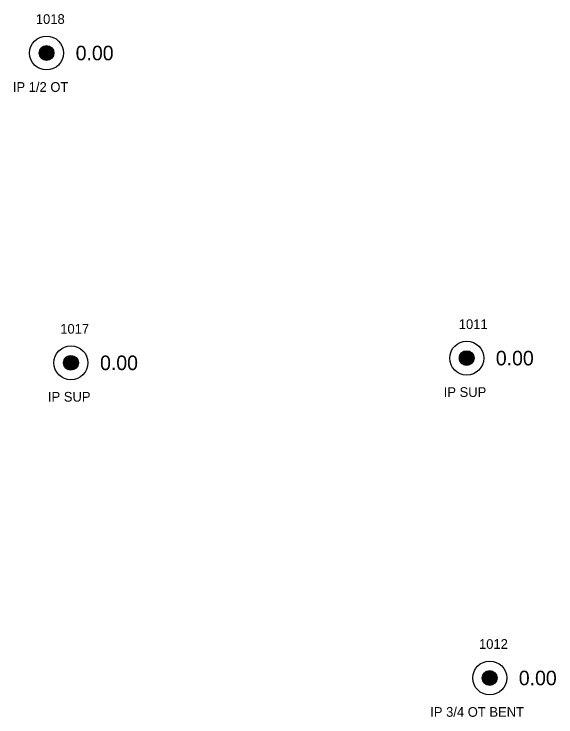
# Model space of a CAD drawing. Extents: x 1529475 to 1532053, y 876698 to 877911.
# Drawn here: x 1529474.6 to 1529530.4, y 877491.7 to 877564.1 of the extents above; entities that cross this region are included whole.
import ezdxf

# ---------------------------------------------------------------- set-up
doc = ezdxf.new("R2010")
doc.units = 0
for name, color, linetype in [('RD_EX_DV_Prop_txCode', 7, 'Continuous'), ('RD_EX_DV_PropPin', 7, 'Continuous'), ('RD_EX_TX_DV_Prop_ELEV', 7, 'Continuous'), ('RD_SMD_Locator', 7, 'Continuous')]:
    doc.layers.add(name, color=color, linetype=linetype)

msp = doc.modelspace()

# ---------------------------------------------------------------- linework, layer by layer
at = {"layer": 'RD_EX_DV_PropPin'}
for p, q in [((1529477.764, 877559.334), (1529477.764, 877560.815)), ((1529477.799, 877559.327), (1529477.799, 877560.823)), ((1529477.834, 877559.321), (1529477.834, 877560.828)), ((1529477.869, 877559.317), (1529477.869, 877560.832)), ((1529477.904, 877559.314), (1529477.904, 877560.835)), ((1529477.939, 877559.314), (1529477.939, 877560.836)), ((1529477.974, 877559.314), (1529477.974, 877560.835)), ((1529478.009, 877559.317), (1529478.009, 877560.832)), ((1529478.044, 877559.321), (1529478.044, 877560.828)), ((1529478.079, 877559.327), (1529478.079, 877560.823)), ((1529478.114, 877559.334), (1529478.114, 877560.815)), ((1529477.204, 877559.878), (1529477.204, 877560.271)), ((1529477.239, 877559.777), (1529477.239, 877560.373)), ((1529477.274, 877559.705), (1529477.274, 877560.444)), ((1529477.309, 877559.648), (1529477.309, 877560.501)), ((1529477.344, 877559.6), (1529477.344, 877560.549)), ((1529477.379, 877559.56), (1529477.379, 877560.59)), ((1529477.414, 877559.524), (1529477.414, 877560.625)), ((1529477.449, 877559.492), (1529477.449, 877560.657)), ((1529477.484, 877559.465), (1529477.484, 877560.684)), ((1529477.519, 877559.44), (1529477.519, 877560.709)), ((1529477.554, 877559.418), (1529477.554, 877560.731)), ((1529477.589, 877559.399), (1529477.589, 877560.75)), ((1529477.624, 877559.382), (1529477.624, 877560.767)), ((1529477.659, 877559.367), (1529477.659, 877560.782)), ((1529477.694, 877559.354), (1529477.694, 877560.795)), ((1529477.729, 877559.343), (1529477.729, 877560.806)), ((1529478.149, 877559.343), (1529478.149, 877560.806)), ((1529478.184, 877559.354), (1529478.184, 877560.795)), ((1529478.219, 877559.367), (1529478.219, 877560.782)), ((1529478.254, 877559.382), (1529478.254, 877560.767)), ((1529478.289, 877559.399), (1529478.289, 877560.75)), ((1529478.324, 877559.418), (1529478.324, 877560.731)), ((1529478.359, 877559.44), (1529478.359, 877560.709)), ((1529478.394, 877559.465), (1529478.394, 877560.684)), ((1529478.429, 877559.492), (1529478.429, 877560.657)), ((1529478.464, 877559.524), (1529478.464, 877560.625)), ((1529478.5, 877559.56), (1529478.5, 877560.59)), ((1529478.535, 877559.6), (1529478.535, 877560.549)), ((1529478.57, 877559.648), (1529478.57, 877560.501)), ((1529478.605, 877559.705), (1529478.605, 877560.444)), ((1529478.64, 877559.777), (1529478.64, 877560.373)), ((1529478.675, 877559.878), (1529478.675, 877560.271)), ((1529520.568, 877528.268), (1529520.568, 877529.007)), ((1529520.603, 877528.211), (1529520.603, 877529.064)), ((1529520.638, 877528.163), (1529520.638, 877529.112)), ((1529520.673, 877528.122), (1529520.673, 877529.152)), ((1529520.708, 877528.087), (1529520.708, 877529.188)), ((1529520.743, 877528.055), (1529520.743, 877529.22)), ((1529520.778, 877528.028), (1529520.778, 877529.247)), ((1529520.813, 877528.003), (1529520.813, 877529.272)), ((1529520.848, 877527.981), (1529520.848, 877529.294)), ((1529520.883, 877527.962), (1529520.883, 877529.313)), ((1529520.918, 877527.945), (1529520.918, 877529.33)), ((1529520.953, 877527.93), (1529520.953, 877529.345)), ((1529520.988, 877527.917), (1529520.988, 877529.358)), ((1529521.023, 877527.906), (1529521.023, 877529.369)), ((1529521.058, 877527.897), (1529521.058, 877529.378)), ((1529521.093, 877527.889), (1529521.093, 877529.385)), ((1529521.128, 877527.884), (1529521.128, 877529.391)), ((1529521.163, 877527.88), (1529521.163, 877529.395)), ((1529521.198, 877527.877), (1529521.198, 877529.398)), ((1529521.233, 877527.876), (1529521.233, 877529.398)), ((1529521.268, 877527.877), (1529521.268, 877529.398)), ((1529521.303, 877527.88), (1529521.303, 877529.395)), ((1529521.338, 877527.884), (1529521.338, 877529.391)), ((1529521.373, 877527.889), (1529521.373, 877529.385)), ((1529521.408, 877527.897), (1529521.408, 877529.378)), ((1529521.443, 877527.906), (1529521.443, 877529.369)), ((1529521.478, 877527.917), (1529521.478, 877529.358)), ((1529521.513, 877527.93), (1529521.513, 877529.345)), ((1529521.548, 877527.945), (1529521.548, 877529.33)), ((1529521.583, 877527.962), (1529521.583, 877529.313)), ((1529521.618, 877527.981), (1529521.618, 877529.294)), ((1529521.653, 877528.003), (1529521.653, 877529.272)), ((1529521.688, 877528.028), (1529521.688, 877529.247)), ((1529521.723, 877528.055), (1529521.723, 877529.22)), ((1529521.758, 877528.087), (1529521.758, 877529.188)), ((1529521.794, 877528.122), (1529521.794, 877529.152)), ((1529521.829, 877528.163), (1529521.829, 877529.112)), ((1529521.864, 877528.211), (1529521.864, 877529.064)), ((1529521.899, 877528.268), (1529521.899, 877529.007)), ((1529479.716, 877527.957), (1529479.716, 877528.349)), ((1529479.751, 877527.855), (1529479.751, 877528.451)), ((1529479.787, 877527.784), (1529479.787, 877528.523)), ((1529479.822, 877527.727), (1529479.822, 877528.58)), ((1529479.857, 877527.679), (1529479.857, 877528.627)), ((1529479.892, 877527.638), (1529479.892, 877528.668)), ((1529479.927, 877527.603), (1529479.927, 877528.704)), ((1529479.962, 877527.571), (1529479.962, 877528.735)), ((1529479.997, 877527.543), (1529479.997, 877528.763)), ((1529480.032, 877527.519), (1529480.032, 877528.788)), ((1529480.067, 877527.497), (1529480.067, 877528.81)), ((1529480.102, 877527.478), (1529480.102, 877528.829)), ((1529480.137, 877527.461), (1529480.137, 877528.846)), ((1529480.172, 877527.446), (1529480.172, 877528.861)), ((1529480.207, 877527.433), (1529480.207, 877528.874)), ((1529480.242, 877527.422), (1529480.242, 877528.885)), ((1529480.277, 877527.413), (1529480.277, 877528.894)), ((1529480.312, 877527.405), (1529480.312, 877528.901)), ((1529480.347, 877527.4), (1529480.347, 877528.907)), ((1529480.382, 877527.396), (1529480.382, 877528.911)), ((1529480.417, 877527.393), (1529480.417, 877528.914)), ((1529480.452, 877527.392), (1529480.452, 877528.914)), ((1529480.487, 877527.393), (1529480.487, 877528.914)), ((1529480.522, 877527.396), (1529480.522, 877528.911)), ((1529480.557, 877527.4), (1529480.557, 877528.907)), ((1529480.592, 877527.405), (1529480.592, 877528.901)), ((1529480.627, 877527.413), (1529480.627, 877528.894)), ((1529480.662, 877527.422), (1529480.662, 877528.885)), ((1529480.697, 877527.433), (1529480.697, 877528.874)), ((1529480.732, 877527.446), (1529480.732, 877528.861)), ((1529480.767, 877527.461), (1529480.767, 877528.846)), ((1529480.802, 877527.478), (1529480.802, 877528.829)), ((1529480.837, 877527.497), (1529480.837, 877528.81)), ((1529480.872, 877527.519), (1529480.872, 877528.788)), ((1529480.907, 877527.543), (1529480.907, 877528.763)), ((1529480.942, 877527.571), (1529480.942, 877528.735)), ((1529480.977, 877527.603), (1529480.977, 877528.704)), ((1529481.012, 877527.638), (1529481.012, 877528.668)), ((1529481.047, 877527.679), (1529481.047, 877528.627)), ((1529481.082, 877527.727), (1529481.082, 877528.58)), ((1529481.117, 877527.784), (1529481.117, 877528.523)), ((1529481.152, 877527.855), (1529481.152, 877528.451)), ((1529481.187, 877527.957), (1529481.187, 877528.349)), ((1529520.498, 877528.441), (1529520.498, 877528.834)), ((1529520.533, 877528.339), (1529520.533, 877528.935)), ((1529521.934, 877528.339), (1529521.934, 877528.935)), ((1529521.969, 877528.441), (1529521.969, 877528.834)), ((1529523.249, 877495), (1529523.249, 877496.351)), ((1529523.284, 877494.983), (1529523.284, 877496.368)), ((1529523.319, 877494.968), (1529523.319, 877496.383)), ((1529523.354, 877494.955), (1529523.354, 877496.396)), ((1529523.389, 877494.944), (1529523.389, 877496.407)), ((1529523.424, 877494.935), (1529523.424, 877496.416)), ((1529523.459, 877494.928), (1529523.459, 877496.424)), ((1529523.494, 877494.922), (1529523.494, 877496.429)), ((1529523.529, 877494.918), (1529523.529, 877496.433)), ((1529523.564, 877494.915), (1529523.564, 877496.436)), ((1529523.599, 877494.915), (1529523.599, 877496.437)), ((1529523.634, 877494.915), (1529523.634, 877496.436)), ((1529523.669, 877494.918), (1529523.669, 877496.433)), ((1529523.704, 877494.922), (1529523.704, 877496.429)), ((1529523.739, 877494.928), (1529523.739, 877496.424)), ((1529523.774, 877494.935), (1529523.774, 877496.416)), ((1529523.809, 877494.944), (1529523.809, 877496.407)), ((1529523.844, 877494.955), (1529523.844, 877496.396)), ((1529523.879, 877494.968), (1529523.879, 877496.383)), ((1529523.914, 877494.983), (1529523.914, 877496.368)), ((1529523.949, 877495), (1529523.949, 877496.351)), ((1529522.863, 877495.48), (1529522.863, 877495.872)), ((1529522.898, 877495.378), (1529522.898, 877495.974)), ((1529522.934, 877495.306), (1529522.934, 877496.045)), ((1529522.969, 877495.249), (1529522.969, 877496.102)), ((1529523.004, 877495.202), (1529523.004, 877496.15)), ((1529523.039, 877495.161), (1529523.039, 877496.191)), ((1529523.074, 877495.125), (1529523.074, 877496.226)), ((1529523.109, 877495.094), (1529523.109, 877496.258)), ((1529523.144, 877495.066), (1529523.144, 877496.286)), ((1529523.179, 877495.041), (1529523.179, 877496.31)), ((1529523.214, 877495.019), (1529523.214, 877496.332)), ((1529523.984, 877495.019), (1529523.984, 877496.332)), ((1529524.019, 877495.041), (1529524.019, 877496.31)), ((1529524.054, 877495.066), (1529524.054, 877496.286)), ((1529524.089, 877495.094), (1529524.089, 877496.258)), ((1529524.124, 877495.125), (1529524.124, 877496.226)), ((1529524.159, 877495.161), (1529524.159, 877496.191)), ((1529524.194, 877495.202), (1529524.194, 877496.15)), ((1529524.229, 877495.249), (1529524.229, 877496.102)), ((1529524.264, 877495.306), (1529524.264, 877496.045)), ((1529524.299, 877495.378), (1529524.299, 877495.974)), ((1529524.334, 877495.48), (1529524.334, 877495.872))]:
    msp.add_line(p, q, dxfattribs=at)
for centre, radius in [((1529477.939, 877560.075), 1.75), ((1529477.939, 877560.075), 0.761), ((1529480.452, 877528.153), 1.75), ((1529521.233, 877528.637), 1.75), ((1529521.233, 877528.637), 0.761), ((1529480.452, 877528.153), 0.761), ((1529523.599, 877495.676), 1.75), ((1529523.599, 877495.676), 0.761)]:
    msp.add_circle(centre, radius, dxfattribs=at)
at = {"layer": 'RD_SMD_Locator'}
for centre in [(1529477.939, 877560.075), (1529480.452, 877528.153), (1529521.233, 877528.637), (1529523.599, 877495.676)]:
    msp.add_circle(centre, 0.15, dxfattribs=at)

# ---------------------------------------------------------------- texts
at = {"layer": 'RD_EX_DV_Prop_txCode'}
for s, p in [('1018', (1529476.837, 877563.075)), ('IP 1/2 OT', (1529474.467, 877556.075)), ('1011', (1529520.414, 877531.637)), ('1017', (1529479.349, 877531.153)), ('IP SUP', (1529518.863, 877524.637)), ('IP SUP', (1529478.082, 877524.153)), ('1012', (1529522.496, 877498.676)), ('IP 3/4 OT BENT', (1529517.473, 877491.676))]:
    msp.add_text(s, height=1, dxfattribs=at).set_placement(p)
at = {"layer": 'RD_EX_TX_DV_Prop_ELEV'}
for p in [(1529480.939, 877559.325), (1529524.233, 877527.887), (1529483.452, 877527.403), (1529526.599, 877494.926)]:
    msp.add_text('0.00', height=1.5, dxfattribs=at).set_placement(p)

doc.saveas('drawing.dxf')
